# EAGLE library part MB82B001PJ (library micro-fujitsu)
MICROCONTROLLER/MEMORY DEVICE
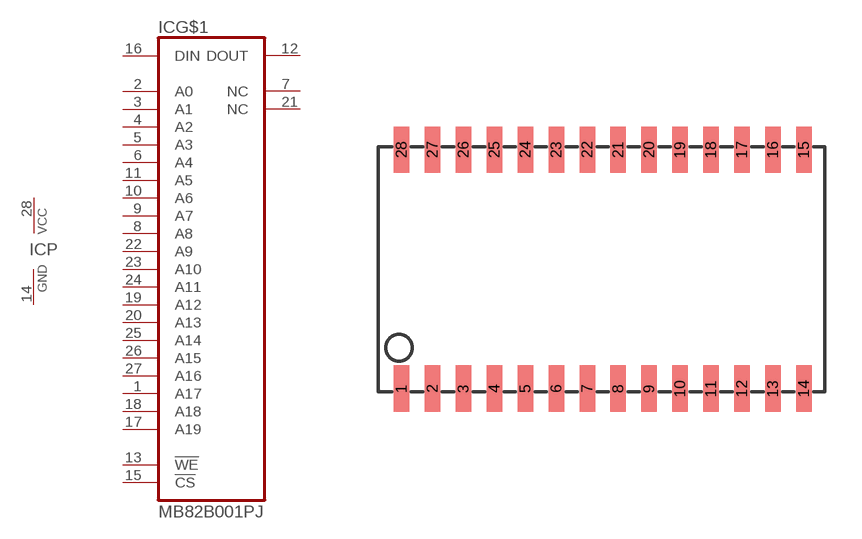
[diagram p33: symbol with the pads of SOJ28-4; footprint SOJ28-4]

Designator prefix IC; gates G$1=MB82B001 P=VCC-GND

## MB82B001PJ (OC_FARNELL: unknown; OC_NEWARK: unknown)  [SOJ28-4]
1  G$1:A17  in
2  G$1:A0  in
3  G$1:A1  in
4  G$1:A2  in
5  G$1:A3  in
6  G$1:A4  in
7  G$1:NC  nc
8  G$1:A8  in
9  G$1:A7  in
10  G$1:A6  in
11  G$1:A5  in
12  G$1:DOUT  out
13  G$1:!WE  in
14  P:GND  pwr
15  G$1:!CS  in
16  G$1:DIN  in
17  G$1:A19  in
18  G$1:A18  in
19  G$1:A12  in
20  G$1:A13  in
21  G$1:NC  nc
22  G$1:A9  in
23  G$1:A10  in
24  G$1:A11  in
25  G$1:A14  in
26  G$1:A15  in
27  G$1:A16  in
28  P:VCC  pwr

## Footprint SOJ28-4 (pad centres in mm)
Small Outline J-Bend
smd 0.635 x 1.905: 1 -8.255,-4.902; 2 -6.985,-4.902; 3 -5.715,-4.902; 4 -4.445,-4.902; 5 -3.175,-4.902; 6 -1.905,-4.902; 7 -0.635,-4.902; 8 0.635,-4.902; 9 1.905,-4.902; 10 3.175,-4.902; 11 4.445,-4.902; 12 5.715,-4.902; 13 6.985,-4.902; 14 8.255,-4.902; 15 8.255,4.902; 16 6.985,4.902; 17 5.715,4.902; 18 4.445,4.902; 19 3.175,4.902; 20 1.905,4.902; 21 0.635,4.902; 22 -0.635,4.902; 23 -1.905,4.902; 24 -3.175,4.902; 25 -4.445,4.902; 26 -5.715,4.902; 27 -6.985,4.902; 28 -8.255,4.902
